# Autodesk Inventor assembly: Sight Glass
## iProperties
Created: 2007-11
Part Number: Sight Glass
Document SubType Name: Assembly
Designer: CM
Mass: 8.51031 g
Surface Area: 65.3056 cm^2
Volume: 8.21977 cm^3
Density: 1.03535 g/cm^3
Author: CM
